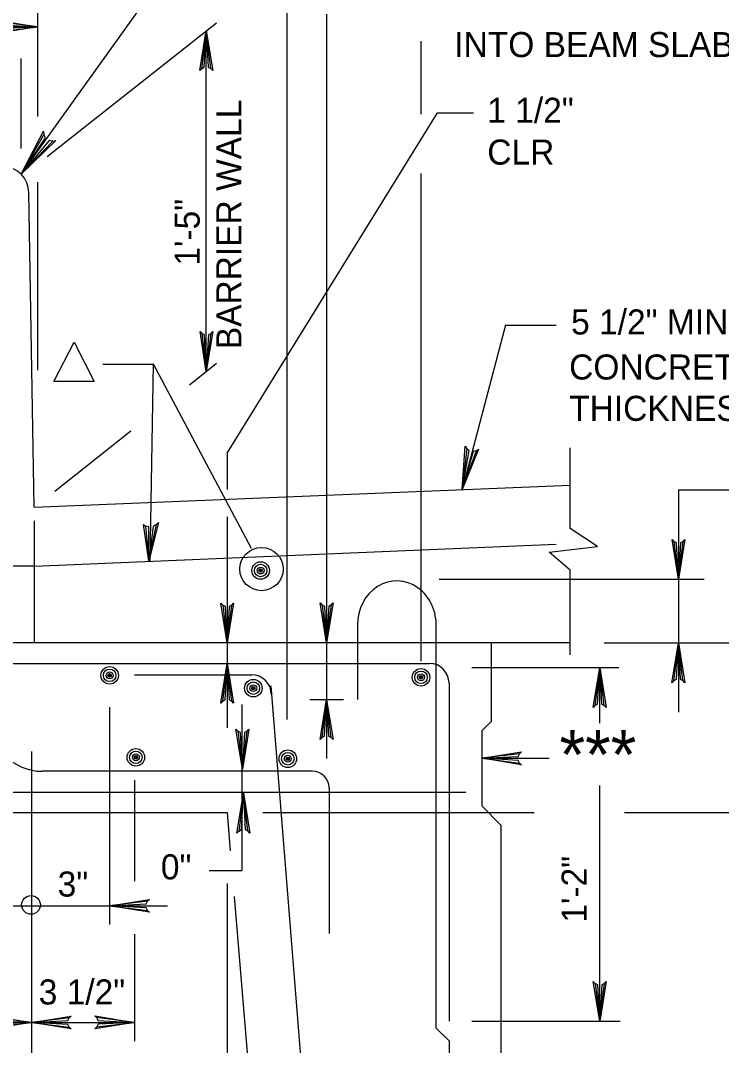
# Model space of a CAD drawing. Extents: x 642009 to 642864, y 298232 to 300014.
# Drawn here: x 642625.2 to 642709.1, y 298606.3 to 298729.1 of the extents above; entities that cross this region are included whole.
import ezdxf

# ---------------------------------------------------------------- set-up
doc = ezdxf.new("R2010")
doc.units = 0
for name, color, linetype in [('1', 7, 'Continuous'), ('10', 7, 'Continuous'), ('15', 7, 'Continuous'), ('2', 7, 'Continuous'), ('22', 7, 'Continuous'), ('3', 7, 'Continuous')]:
    doc.layers.add(name, color=color, linetype=linetype)

msp = doc.modelspace()

# ---------------------------------------------------------------- linework, layer by layer
at = {"layer": '1'}
for p, q in [((642626.89, 298670.77), (642626.22, 298708.41)), ((642691.02, 298668.24), (642691.02, 298677.91)), ((642626.89, 298670.77), (642691.02, 298673.44)), ((642626.89, 298669.17), (642626.89, 298654.55)), ((642691.02, 298653.11), (642691.02, 298663.26)), ((642691.02, 298654.55), (642572.64, 298654.55)), ((642681.61, 298645.17), (642681.61, 298654.55)), ((642681.61, 298645.17), (642680.43, 298644)), ((642680.43, 298644), (642680.43, 298635.02)), ((642680.43, 298635.02), (642682.78, 298632.67)), ((642603.1, 298634.24), (642649.97, 298634.24)), ((642649.97, 298634.24), (642650.35, 298629.63)), ((642682.78, 298581.71), (642682.78, 298632.67)), ((642650.81, 298624.19), (642654.33, 298581.89))]:
    msp.add_line(p, q, dxfattribs=at)
msp.add_lwpolyline([(642629.24, 298685.84), (642631.65, 298690.54), (642634.06, 298685.84)], close=True, dxfattribs=at)
for points in [[(642691.02, 298663.26), (642688.52, 298665.41), (642694.31, 298666.09), (642691.02, 298668.24)], [(642684.97, 298640.15), (642684.81, 298640.48), (642680.43, 298640.72), (642684.97, 298640.15), (642685.21, 298639.96), (642680.43, 298640.72), (642684.8, 298640.94), (642684.96, 298641.27), (642680.43, 298640.72), (642685.21, 298641.48), (642684.96, 298641.27)]]:
    msp.add_lwpolyline(points, dxfattribs=at)
msp.add_circle((642626.5, 298623.17), 1.12, dxfattribs=at)
msp.add_arc((642623.11, 298708.45), 3.12, 359.4063, 88.777, dxfattribs=at)
at = {"layer": '10'}
msp.add_line((642626.54, 298641.54), (642626.54, 298595.57), dxfattribs=at)
at = {"layer": '15'}
for p, q in [((642626.89, 298663.74), (642689.36, 298666.34)), ((642626.89, 298663.74), (642575.19, 298663.74)), ((642665.57, 298656.67), (642665.57, 298647.75)), ((642674.96, 298656.37), (642674.96, 298608.46)), ((642578.89, 298652.09), (642674.18, 298652.09)), ((642638.87, 298650.73), (642652.91, 298650.73)), ((642679.27, 298651.59), (642696.85, 298651.59)), ((642676.53, 298649.74), (642676.53, 298609.24)), ((642655.2, 298649.39), (642660.09, 298588.14)), ((642660.18, 298639.17), (642627.85, 298639.17)), ((642572.84, 298636.68), (642678.54, 298636.68)), ((642679.27, 298609.24), (642697.02, 298609.24)), ((642676.53, 298606.9), (642674.96, 298608.46)), ((642676.53, 298606.9), (642676.53, 298588.15))]:
    msp.add_line(p, q, dxfattribs=at)
for points in [[(642649.41, 298647.55), (642649.74, 298647.72), (642649.98, 298652.09), (642649.41, 298647.55), (642649.21, 298647.31), (642649.98, 298652.09), (642650.2, 298647.72), (642650.52, 298647.56), (642649.98, 298652.09), (642650.74, 298647.31), (642650.52, 298647.56)], [(642661.31, 298643.21), (642661.64, 298643.38), (642661.88, 298647.75), (642661.31, 298643.21), (642661.11, 298642.98), (642661.88, 298647.75), (642662.09, 298643.39), (642662.42, 298643.23), (642661.88, 298647.75), (642662.64, 298642.98), (642662.42, 298643.23)], [(642651.35, 298632.02), (642651.68, 298632.19), (642651.92, 298636.56), (642651.35, 298632.02), (642651.15, 298631.78), (642651.92, 298636.56), (642652.13, 298632.19), (642652.46, 298632.03), (642651.92, 298636.56), (642652.68, 298631.78), (642652.46, 298632.03)]]:
    msp.add_lwpolyline(points, dxfattribs=at)
for centre, radius, start, end in [((642674.18, 298649.74), 2.34, 0, 90), ((642652.91, 298648.39), 2.34, 0, 90), ((642627.85, 298645.42), 6.25, 180, 270)]:
    msp.add_arc(centre, radius, start, end, dxfattribs=at)
at = {"layer": '2'}
for p, q in [((642680.43, 298640.72), (642688.51, 298640.72)), ((642662.18, 298637.17), (642662.18, 298619.76)), ((642626.54, 298623.07), (642626.54, 298623.07))]:
    msp.add_line(p, q, dxfattribs=at)
msp.add_arc((642660.18, 298637.17), 2, 0, 90, dxfattribs=at)
msp.add_ellipse((642670.27, 298656.73), major_axis=(0, 5.23), ratio=0.9, start_param=4.644026, end_param=7.865813, dxfattribs=at)
at = {"layer": '22'}
for p, q in [((642627.33, 298717.54), (642627.33, 298751.16)), ((642625.32, 298710.64), (642651.44, 298747.17)), ((642657.17, 298645.37), (642657.17, 298737.58)), ((642661.88, 298729.82), (642661.88, 298654.55)), ((642603.84, 298728.28), (642627.33, 298728.28)), ((642628.44, 298712.76), (642648.71, 298728.79)), ((642647.48, 298687.05), (642647.48, 298727.82)), ((642673.17, 298717.85), (642673.17, 298726.56)), ((642625.33, 298713.73), (642625.33, 298724.5)), ((642649.98, 298677.27), (642675.13, 298718.01)), ((642675.13, 298718.01), (642679.45, 298718.01)), ((642627.33, 298687.2), (642627.33, 298709.7)), ((642673.17, 298652.37), (642673.17, 298710.73)), ((642683.27, 298692.58), (642678.1, 298672.9)), ((642683.27, 298692.58), (642689.35, 298692.58)), ((642635.11, 298687.91), (642641.17, 298687.91)), ((642640.74, 298664.31), (642641.17, 298687.91)), ((642652.9, 298665.86), (642641.17, 298687.91)), ((642645.45, 298685.44), (642648.71, 298688.02)), ((642629.34, 298672.71), (642638.46, 298679.91)), ((642649.98, 298677.27), (642649.98, 298672.91)), ((642703.97, 298672.87), (642703.97, 298662.15)), ((642703.97, 298672.87), (642713.58, 298672.87)), ((642649.98, 298669.65), (642649.98, 298644.38)), ((642675.34, 298662.15), (642707.07, 298662.15)), ((642703.97, 298662.15), (642703.97, 298654.55)), ((642661.88, 298654.55), (642661.88, 298647.75)), ((642695.09, 298654.55), (642731.76, 298654.55)), ((642703.97, 298654.55), (642703.97, 298646.23)), ((642694.55, 298644.93), (642694.55, 298651.59)), ((642651.74, 298647.17), (642651.74, 298627.28)), ((642659.86, 298647.75), (642663.9, 298647.75)), ((642661.88, 298647.75), (642661.88, 298640.7)), ((642635.91, 298646.86), (642635.91, 298620.82)), ((642638.89, 298638.11), (642638.89, 298626)), ((642694.55, 298609.24), (642694.55, 298637.47)), ((642654.25, 298634.24), (642686.73, 298634.24)), ((642697.54, 298634.24), (642720.09, 298634.24)), ((642647.8, 298627.28), (642651.74, 298627.28)), ((642649.97, 298625.74), (642649.97, 298540.27)), ((642609.78, 298623.07), (642626.54, 298623.07)), ((642626.54, 298623.07), (642642.83, 298623.07)), ((642638.89, 298619.68), (642638.89, 298606.86)), ((642614.18, 298609.11), (642626.54, 298609.11)), ((642626.54, 298609.11), (642638.89, 298609.11))]:
    msp.add_line(p, q, dxfattribs=at)
for points in [[(642622.79, 298728.85), (642622.96, 298728.52), (642627.33, 298728.28), (642622.79, 298728.85), (642622.56, 298729.05), (642627.33, 298728.28), (642622.97, 298728.06), (642622.81, 298727.74), (642627.33, 298728.28), (642622.56, 298727.52), (642622.81, 298727.74)], [(642646.91, 298723.28), (642647.24, 298723.45), (642647.48, 298727.82), (642646.91, 298723.28), (642646.71, 298723.05), (642647.48, 298727.82), (642647.7, 298723.45), (642648.03, 298723.29), (642647.48, 298727.82), (642648.24, 298723.05), (642648.03, 298723.29)], [(642629.11, 298714.62), (642628.67, 298714.69), (642625.32, 298710.64), (642629.11, 298714.62), (642629.47, 298714.7), (642625.32, 298710.64), (642628.23, 298715.01), (642628.03, 298715.4), (642625.32, 298710.64), (642627.99, 298715.79), (642628.03, 298715.4)], [(642648.05, 298691.59), (642647.73, 298691.42), (642647.48, 298687.05), (642648.05, 298691.59), (642648.25, 298691.83), (642647.48, 298687.05), (642647.27, 298691.42), (642646.94, 298691.58), (642647.48, 298687.05), (642646.73, 298691.83), (642646.94, 298691.58)], [(642679.81, 298677.54), (642679.42, 298677.44), (642678.1, 298672.9), (642679.81, 298677.54), (642680.07, 298677.73), (642678.1, 298672.9), (642678.94, 298677.55), (642678.64, 298677.79), (642678.1, 298672.9), (642678.47, 298678.11), (642678.64, 298677.79)], [(642641.5, 298668.71), (642641.11, 298668.5), (642640.58, 298664.35), (642641.5, 298668.71), (642641.74, 298668.96), (642640.58, 298664.35), (642640.58, 298668.43), (642640.21, 298668.53), (642640.58, 298664.35), (642639.97, 298668.73), (642640.21, 298668.53)], [(642704.54, 298666.69), (642704.21, 298666.52), (642703.97, 298662.15), (642704.54, 298666.69), (642704.74, 298666.92), (642703.97, 298662.15), (642703.76, 298666.52), (642703.43, 298666.68), (642703.97, 298662.15), (642703.21, 298666.92), (642703.43, 298666.68)], [(642650.55, 298659.07), (642650.22, 298658.9), (642649.98, 298654.53), (642650.55, 298659.07), (642650.75, 298659.3), (642649.98, 298654.53), (642649.77, 298658.9), (642649.44, 298659.05), (642649.98, 298654.53), (642649.22, 298659.3), (642649.44, 298659.05)], [(642662.45, 298659.09), (642662.12, 298658.92), (642661.88, 298654.55), (642662.45, 298659.09), (642662.65, 298659.32), (642661.88, 298654.55), (642661.66, 298658.91), (642661.34, 298659.07), (642661.88, 298654.55), (642661.12, 298659.32), (642661.34, 298659.07)], [(642703.4, 298650.01), (642703.73, 298650.18), (642703.97, 298654.55), (642703.4, 298650.01), (642703.2, 298649.77), (642703.97, 298654.55), (642704.19, 298650.18), (642704.51, 298650.02), (642703.97, 298654.55), (642704.73, 298649.77), (642704.51, 298650.02)], [(642693.98, 298647.05), (642694.31, 298647.22), (642694.55, 298651.59), (642693.98, 298647.05), (642693.78, 298646.82), (642694.55, 298651.59), (642694.76, 298647.22), (642695.09, 298647.06), (642694.55, 298651.59), (642695.31, 298646.82), (642695.09, 298647.06)], [(642652.36, 298643.97), (642652.03, 298643.8), (642651.79, 298639.43), (642652.36, 298643.97), (642652.55, 298644.21), (642651.79, 298639.43), (642651.57, 298643.8), (642651.24, 298643.96), (642651.79, 298639.43), (642651.03, 298644.21), (642651.24, 298643.96)], [(642640.45, 298622.5), (642640.28, 298622.83), (642635.91, 298623.07), (642640.45, 298622.5), (642640.68, 298622.3), (642635.91, 298623.07), (642640.28, 298623.29), (642640.44, 298623.61), (642635.91, 298623.07), (642640.68, 298623.83), (642640.44, 298623.61)], [(642695.12, 298613.78), (642694.79, 298613.61), (642694.55, 298609.24), (642695.12, 298613.78), (642695.32, 298614.01), (642694.55, 298609.24), (642694.33, 298613.61), (642694.01, 298613.77), (642694.55, 298609.24), (642693.79, 298614.01), (642694.01, 298613.77)], [(642622, 298609.68), (642622.17, 298609.35), (642626.54, 298609.11), (642622, 298609.68), (642621.76, 298609.88), (642626.54, 298609.11), (642622.17, 298608.89), (642622.01, 298608.57), (642626.54, 298609.11), (642621.76, 298608.35), (642622.01, 298608.57)], [(642631.08, 298608.54), (642630.91, 298608.87), (642626.54, 298609.11), (642631.08, 298608.54), (642631.31, 298608.34), (642626.54, 298609.11), (642630.9, 298609.32), (642631.06, 298609.65), (642626.54, 298609.11), (642631.31, 298609.87), (642631.06, 298609.65)], [(642634.35, 298609.68), (642634.52, 298609.35), (642638.89, 298609.11), (642634.35, 298609.68), (642634.12, 298609.88), (642638.89, 298609.11), (642634.53, 298608.89), (642634.37, 298608.57), (642638.89, 298609.11), (642634.12, 298608.35), (642634.37, 298608.57)]]:
    msp.add_lwpolyline(points, dxfattribs=at)
msp.add_circle((642654.08, 298663.38), 2.59, dxfattribs=at)
at = {"layer": '3'}
for centre, radius in [((642653.98, 298663.2), 1.05), ((642653.98, 298663.2), 0.75), ((642653.98, 298663.2), 0.41), ((642653.98, 298663.2), 0.207), ((642653.98, 298663.2), 0.0887), ((642635.91, 298650.65), 1.05), ((642635.91, 298650.65), 0.75), ((642635.91, 298650.65), 0.41), ((642635.91, 298650.65), 0.207), ((642635.91, 298650.65), 0.0887), ((642673.17, 298650.42), 1.05), ((642673.17, 298650.42), 0.75), ((642673.17, 298650.42), 0.41), ((642653.1, 298649.12), 1.05), ((642653.1, 298649.12), 0.75), ((642653.1, 298649.12), 0.41), ((642673.17, 298650.42), 0.207), ((642673.17, 298650.42), 0.0887), ((642653.1, 298649.12), 0.207), ((642653.1, 298649.12), 0.0887), ((642639.05, 298640.84), 1.05), ((642639.05, 298640.84), 0.75), ((642639.05, 298640.84), 0.41), ((642639.05, 298640.84), 0.207), ((642639.05, 298640.84), 0.0887), ((642657.23, 298640.67), 1.05), ((642657.23, 298640.67), 0.75), ((642657.23, 298640.67), 0.41), ((642657.23, 298640.67), 0.207), ((642657.23, 298640.67), 0.0887)]:
    msp.add_circle(centre, radius, dxfattribs=at)

# ---------------------------------------------------------------- texts
at = {"layer": '2'}
msp.add_text('***', height=5.88, dxfattribs=at).set_placement((642689.75, 298638.22))
at = {"layer": '22'}
for s, height, rotation, p in [('INTO BEAM SLAB (TYP.)', 2.9997, 360, (642677.15, 298724.67)), ('BARRIER WALL', 2.9997, 90, (642651.68, 298689.7)), ('1\'-5"', 3, 90, (642646.68, 298699.71)), ('5 1/2" MIN.COMPOSITE ', 2.9997, 360, (642691.13, 298691.46)), ('CONCRETE DECK SLAB', 2.9997, 360, (642690.9, 298686.07)), ('THICKNESS "T"', 2.9997, 360, (642690.9, 298681.12)), ('1\'-2"', 3, 90, (642692.99, 298621.05))]:
    msp.add_text(s, height=height, rotation=rotation, dxfattribs=at).set_placement(p)
for s, p in [('1 1/2"', (642681.1, 298716.8)), ('CLR', (642681.1, 298711.8)), ('0"', (642642.04, 298626.23)), ('3"', (642629.69, 298624.17)), ('3 1/2"', (642627.42, 298611.25))]:
    msp.add_text(s, height=3, dxfattribs=at).set_placement(p)

doc.saveas('drawing.dxf')
